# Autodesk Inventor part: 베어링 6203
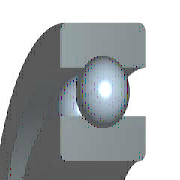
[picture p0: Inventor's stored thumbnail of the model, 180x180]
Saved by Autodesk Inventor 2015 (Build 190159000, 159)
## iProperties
IsCustomPart: 0
Created: 2014-10
Part Number: 베어링 6203
Material: 강철, 연강
Description: 깊은 그루브 볼 베어링
Document SubType Name: Modeling
Standard: KS B 2023
Designer: KYOUNG IL JANG
Standards Organization: KS
Language: ko-KR
Size Designation: 6203 - 17 x 40 x 12
Categories: <MemberInstance><Categories><Category DisplayName="샤프트 부품" InternalName="7f7aeb1f-a693-4053-b835-cee3144e0d98" Mnemonic="SHFT"><Category DisplayName="베어링" Inter
Density: 7.86 g/cm^3
Mass: 64.9809 g
Surface Area: 64.3582 cm^2
Volume: 8.26729 cm^3
Appearance: 노란색
Author: SeoGD™ [www.esajin.kr]
Revision Number: 1
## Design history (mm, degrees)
sketch "스케치" dims "d0" = 5.98 (= -0.26 x WD + 0.26 x BD)
  geometry: L1 (3.01, 14.25)-(8.99, 14.25); L2 (6, 14.25)-(6, 11.26); L3 (6, 14.25)-(6, 17.24); L4 (3.778, 12.249)-(0, 12.249); L5 (0, 8.5)-(12, 8.5); L6 (3.778, 16.251)-(0, 16.251); L7 (0, 20)-(12, 20); L8 (12, 8.5)-(12, 12.249); L9 (8.222, 12.249)-(12, 12.249); L10 (8.222, 16.251)-(12, 16.251); L11 (12, 20)-(12, 16.251); L12 (-1.4, 0)-(8.4, 0) reference; L13 (0, -0.3)-(0, 5.3) reference
  constraints: 22 end point, 4 point on line, 2 collinear, 2 perpendicular, 2 symmetric about line, 1 midpoint, 1 parallel, 14 other
  dimensions: "d9" = 17 diameter of L5 L12 (= WD); "d11" = 40 diameter of L7 L12 (= BD); "d12" = 12 distance between parallel lines of L8 L13 (= KB); "d13" = 24.498 diameter of L9 L12 (= 0.326 x BD + 0.674 x WD)
revolve "본체" stored, may be unused: angle "d6" = 90 deg
revolve "볼" stored, may be unused: angle "d7" = 90 deg
pattern_circular "IDS_ARRAYBALL[SIMPL:T]" dims angle "d3" = 360 deg
body "Solid1"
fillet "모깎기1" dims "d1" = 0.6 (= KRS)
other parameters: "WD" = 17 [user parameter; used in 5 equation terms], "BD" = 40 [user parameter; used in 5 equation terms], "KB" = 12 [user parameter; used in 1 equation term], "KRS" = 0.6 [user parameter; used in 1 equation term], "d4" = 0, "d5" = 0, "d8" = 0, "d14" = 0, "d15" = 0, "BBA" = 0 [user parameter], "BC0" = 4750000 [user parameter], "BC" = 9560000 [user parameter], "WR" = 8.5 (= 0.5 x WD) [user parameter]
